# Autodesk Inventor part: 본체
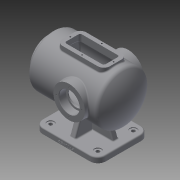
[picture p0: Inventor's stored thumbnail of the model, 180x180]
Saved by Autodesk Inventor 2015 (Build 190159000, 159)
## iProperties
Created: 2021-11
Part Number: 본체
Material: 일반
Document SubType Name: Modeling
Designer: 10259o
Density: 1 g/cm^3
Appearance: 기본값
Author: 10259o
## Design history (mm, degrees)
sketch "스케치1"
  geometry: L1 (80, -65)-(-80, -65); L2 (-80, -65)-(-80, 65); L3 (-80, 65)-(80, 65); L4 (80, 65)-(80, -65); L5 (80, -65)-(-80, 65); L6 (-80, -65)-(80, 65); 1 further point
  constraints: 12 end point, 2 midpoint, 2 parallel, 1 horizontal, 1 perpendicular
  dimensions: "d0" = 160 distance of L1.start L1.end; "d1" = 130 distance of L3.end L1.start
extrude "돌출1" new body sketch "스케치1" distance "d2" = 14; taper "d3" = 0 deg
sketch "스케치10"
  geometry: L1 (0, 0)-(0, 14) reference; 2 further points
  constraints: 1 other
  dimensions: "d49" = 5 distance of point (80, 0) point (80, 5); "d50" = 80 distance from line of L1 point (80, 5)
feature "엠보싱1" sketch "스케치10" dims "d51" = 0.5, "d52" = 0, "d61" = 100, "d62" = 200, "d63" = 65, "d64" = 20, "d65" = 114
sketch "스케치12"
  geometry: L1 (-100, 114)-(100, 114); L2 (100, 114)-(100, 179); L3 (100, 179)-(-75.993, 179); L4 (80, 0)-(80, 14) reference; L5 (80, 0)-(-80, 0) reference; A1 r 100 centre (0, 114) between (-75.993, 179) and (-100, 114); 1 further point
  constraints: 6 end point, 2 perpendicular, 2 point on circle, 1 centre point, 1 horizontal, 1 horizontal alignment
  dimensions: "d61" = 100 radius of A1; "d62" = 200 distance of L1.start L1.end; "d63" = 65 distance of L1.end L2.end; "d64" = 20 distance between parallel lines of L2 L4; "d65" = 114 distance between parallel lines of L1 L5
revolve "회전1" sketch "스케치12" stored, may be unused: angle "d66" = 90 deg
fillet "모깎기1" dims "d67" = 10
feature "쉘1" dims "d68" = 10
sketch "스케치13"
  geometry: C1 r 55 at (0, 0) reference; C2 r 65 at (0, 0) reference; C3 r 55 at (0, 0); 1 further point
  constraints: 1 centre point, 1 coincident
  dimensions: "d69" = 110 diameter of C3
extrude "돌출8" join sketch "스케치13" distance "d70" = 15; taper "d71" = 0 deg
sketch "스케치14"
  geometry: C1 r 65 at (0, 0) reference; C2 r 47.5 at (0, 0); 1 further point
  constraints: 1 centre point, 1 coincident
  dimensions: "d72" = 95 diameter of C2
extrude "돌출9" join sketch "스케치14" distance "d73" = 10; taper "d74" = 0 deg
sketch "스케치15"
  geometry: C1 r 47.5 at (0, 0) reference; C2 r 32.5 at (0, 0); 1 further point
  constraints: 1 centre point, 1 coincident
  dimensions: "d75" = 65 diameter of C2
extrude "돌출10" cut sketch "스케치15" distance "d76" = 25; taper "d77" = 0 deg
sketch "스케치16"
  geometry: C1 r 32.5 at (0, 0) reference; 2 further points
  constraints: 1 vertical alignment
  dimensions: "d78" = 40 distance of C1.centre point (0, 40)
hole "구멍3" sketch "스케치16" at (0, 40) diameter "d79" = 3.242; stored, may be unused: countersink angle "d83" = 90 deg, drill point angle "d85" = 118 deg; dims "d80" = 11, "d81" = 52, "d82" = 18, "d84" = 13
sketch "스케치17"
  geometry: L1 (-71.239, 179)-(100, 179) reference; L2 (100, 179)-(100, 161.5) reference; L3 (100, 161.5)-(110, 161.5) reference; L4 (110, 161.5)-(110, 155.621) reference; L5 (110, 155.621)-(97, 155.621) reference; L6 (97, 155.621)-(96.026, 154) reference; L7 (96.026, 154)-(97, 152.379) reference; L8 (97, 152.379)-(110, 152.379) reference; L9 (110, 152.379)-(110, 146.5) reference; L10 (110, 146.5)-(85, 146.5) reference; L11 (85, 146.5)-(85, 169) reference; L12 (85, 169)-(-71.239, 169) reference; L13 (-71.239, 59)-(85, 59) reference; L14 (85, 59)-(85, 81.5) reference; L15 (85, 81.5)-(110, 81.5) reference; L16 (110, 81.5)-(110, 75.621) reference; L17 (110, 75.621)-(97, 75.621) reference; L18 (97, 75.621)-(96.026, 74) reference; L19 (96.026, 74)-(97, 72.379) reference; L20 (97, 72.379)-(110, 72.379) reference; L21 (110, 72.379)-(110, 66.5) reference; L22 (110, 66.5)-(100, 66.5) reference; L23 (100, 66.5)-(100, 49) reference; L24 (100, 49)-(-71.239, 49) reference; L25 (-80, 0)-(-80, 14) reference; L26 (-80, 14)-(80, 14) reference; L27 (80, 14)-(80, 0) reference; L28 (80, 0)-(-80, 0) reference; C1 r 40 at (-17, 114); A1 r 100 centre (0, 114) between (-79.154, 175.111) and (-79.154, 52.889) reference; A2 r 10 centre (-71.239, 169) between (-71.239, 179) and (-79.154, 175.111) reference; A3 r 90 centre (0, 114) between (-71.239, 169) and (-71.239, 59) reference; A4 r 10 centre (-71.239, 59) between (-79.154, 52.889) and (-71.239, 49) reference; 1 further point
  constraints: 1 centre point
  dimensions: "d89" = 80 diameter of C1; "d90" = 114 distance from line of L28 C1.centre; "d91" = 127 horizontal distance of L16.end C1.centre
extrude "돌출11" join sketch "스케치17" stored distance "d92" = 150; taper "d93" = 0 deg
sketch "스케치18"
  geometry: C1 r 40 at (0, 0) reference; C2 r 21 at (0, 0); 1 further point
  constraints: 1 centre point, 1 coincident
  dimensions: "d94" = 42 diameter of C2
extrude "돌출12" cut sketch "스케치18" distance "d95" = 18; taper "d96" = 0 deg
sketch "스케치19"
  geometry: C1 r 40 at (0, 0) reference; 1 further point
hole "구멍4" sketch "스케치19" at (0, 0) diameter "d97" = 42; stored, may be unused: countersink angle "d101" = 90 deg, drill point angle "d103" = 118 deg; dims "d98" = 11, "d99" = 52, "d100" = 18, "d102" = 13
sketch "스케치20"
  geometry: C1 r 21 at (0, 0) reference; 2 further points
  constraints: 1 vertical alignment
  dimensions: "d104" = 32.5 distance of C1.centre point (0, 32.5)
hole "구멍5" sketch "스케치20" at (0, 32.5) diameter "d105" = 3.242; stored, may be unused: countersink angle "d109" = 90 deg, drill point angle "d111" = 118 deg; dims "d106" = 11, "d107" = 52, "d108" = 18, "d110" = 13
node "작업 평면2"
sketch "스케치21"
  geometry: L1 (60, -30)-(-60, -30); L2 (-60, -30)-(-60, 30); L3 (-60, 30)-(60, 30); L4 (60, 30)-(60, -30); L5 (60, -30)-(-60, 30); L6 (-60, -30)-(60, 30); 1 further point
  constraints: 12 end point, 2 midpoint, 2 parallel, 1 horizontal, 1 perpendicular
  dimensions: "d116" = 120 distance of L2.end L3.end; "d117" = 60 distance of L1.end L2.end
extrude "돌출13" join sketch "스케치21" stored distance "d118" = 18; taper "d119" = 0 deg
fillet "모깎기2" dims "d120" = 15
sketch "스케치22"
  geometry: L1 (-45, 30)-(45, 30) reference; L2 (-60, -15)-(-60, 15) reference; L3 (45, -30)-(-45, -30) reference; L4 (60, 15)-(60, -15) reference; L5 (50, 15)-(50, -15); L6 (45, -20)-(-45, -20); L7 (-50, -15)-(-50, 15); L8 (-45, 20)-(45, 20); A1 r 15 centre (45, 15) between (60, 15) and (45, 30) reference; A2 r 15 centre (-45, 15) between (-45, 30) and (-60, 15) reference; A3 r 15 centre (-45, -15) between (-60, -15) and (-45, -30) reference; A4 r 15 centre (45, -15) between (45, -30) and (60, -15) reference; A5 r 5 centre (45, 15) between (50, 15) and (45, 20); A6 r 5 centre (45, -15) between (45, -20) and (50, -15); A7 r 5 centre (-45, -15) between (-50, -15) and (-45, -20); A8 r 5 centre (-45, 15) between (-45, 20) and (-50, 15); 1 further point
  constraints: 8 end point, 8 point on circle, 4 centre point, 7 other
  dimensions: "d121" = 10 distance between parallel lines of L1 L8
extrude "돌출14" cut sketch "스케치22" distance "d122" = 70; taper "d123" = 0 deg
sketch "스케치23"
  geometry: 2 further points
  constraints: 1 vertical alignment
  dimensions: "d124" = 25 distance of point (0, 0) point (0, 25)
hole "구멍6" sketch "스케치23" at (0, 25) diameter "d125" = 3.242; stored, may be unused: countersink angle "d129" = 90 deg, drill point angle "d131" = 118 deg; dims "d126" = 9, "d127" = 52, "d128" = 18, "d130" = 11
sketch "스케치24"
  geometry: 2 further points
  constraints: 1 horizontal alignment
  dimensions: "d132" = 55 distance of point (0, 0) point (-55, 0)
hole "구멍7" sketch "스케치24" at (-55, 0) diameter "d133" = 3.242; stored, may be unused: countersink angle "d137" = 90 deg, drill point angle "d139" = 118 deg; dims "d134" = 9, "d135" = 52, "d136" = 18, "d138" = 11
sketch "스케치25"
  geometry: L1 (-65.5, 6.971)-(-65.5, 7.385) reference; L2 (-65.5, 7.385)-(-65, 7.385) reference; L3 (-65, 7.385)-(-65, 14) reference; L4 (-65, 14)-(65, 14) reference; L5 (65, 14)-(65, 0) reference; L6 (65, 0)-(-65, 0) reference; L7 (-65, 0)-(-65, 6.971) reference; L8 (-65, 6.971)-(-65.5, 6.971) reference; L9 (-20, 184)-(-20, 165.235) reference; L10 (-41.4, 150.208)-(-20, 150.208) reference; L11 (-20, 150.208)-(-20, 126.329) reference; L12 (-20, 126.329)-(-75, 126.329) reference; L13 (-75, 126.329)-(-75, 150.208) reference; L14 (-75, 150.208)-(-53.981, 150.208) reference; L15 (-30, 171.663)-(-30, 184) reference; L16 (-30, 184)-(-26.621, 184) reference; L17 (-26.621, 184)-(-26.621, 173) reference; L18 (-26.621, 173)-(-25, 172.026) reference; L19 (-25, 172.026)-(-23.379, 173) reference; L20 (-23.379, 173)-(-23.379, 184) reference; L21 (-23.379, 184)-(-20, 184) reference; L22 (20, 165.235)-(20, 184) reference; L23 (20, 184)-(23.379, 184) reference; L24 (23.379, 184)-(23.379, 173) reference; L25 (23.379, 173)-(25, 172.026) reference; L26 (25, 172.026)-(26.621, 173) reference; L27 (26.621, 173)-(26.621, 184) reference; L28 (26.621, 184)-(30, 184) reference; L29 (30, 184)-(30, 171.663) reference; L30 (53.981, 150.208)-(75, 150.208) reference; L31 (75, 150.208)-(75, 133.672) reference; L32 (75, 133.672)-(57, 133.672) reference; L33 (57, 133.672)-(57, 126.329) reference; L34 (57, 126.329)-(20, 126.329) reference; L35 (20, 126.329)-(20, 150.208) reference; L36 (20, 150.208)-(41.4, 150.208) reference; L37 (41.4, 77.792)-(-41.4, 77.792) reference; L38 (-75, 101.671)-(57, 101.671) reference; L39 (57, 101.671)-(57, 94.328) reference; L40 (57, 94.328)-(75, 94.328) reference; L41 (75, 94.328)-(75, 77.792) reference; L42 (75, 77.792)-(53.981, 77.792) reference; L43 (-53.981, 77.792)-(-75, 77.792) reference; L44 (-75, 77.792)-(-75, 101.671) reference; C1 r 55 at (0, 114); A1 r 55 centre (0, 114) between (-20, 165.235) and (-41.4, 150.208) reference; A2 r 65 centre (0, 114) between (-30, 171.663) and (-53.981, 150.208) reference; A3 r 65 centre (0, 114) between (53.981, 150.208) and (30, 171.663) reference; A4 r 55 centre (0, 114) between (41.4, 150.208) and (20, 165.235) reference; A5 r 55 centre (0, 114) between (-41.4, 77.792) and (41.4, 77.792) reference; A6 r 65 centre (0, 114) between (-53.981, 77.792) and (53.981, 77.792) reference; 1 further point
  constraints: 1 centre point, 1 coincident
  dimensions: "d140" = 110 diameter of C1
extrude "돌출15" cut sketch "스케치25" stored distance "d141" = 130; taper "d142" = 0 deg
fillet "모깎기3" dims "d149" = 20
sketch "스케치27"
  geometry: L1 (-60, 65)-(60, 65) reference; L2 (80, 45)-(80, -45) reference; L3 (60, -65)-(-60, -65) reference; L4 (-80, -45)-(-80, 45) reference; A1 r 20 centre (60, 45) between (80, 45) and (60, 65) reference; A2 r 20 centre (-60, 45) between (-60, 65) and (-80, 45) reference; A3 r 20 centre (60, 45) between (80, 45) and (60, 65) reference; A4 r 20 centre (60, -45) between (60, -65) and (80, -45) reference; A5 r 20 centre (-60, -45) between (-80, -45) and (-60, -65) reference; 1 further point
hole "구멍8" sketch "스케치27" at (60, 45) diameter "d150" = 9; stored, may be unused: countersink angle "d154" = 90 deg, drill point angle "d156" = 118 deg; dims "d151" = 8, "d152" = 18, "d153" = 2, "d155" = 14
sketch "스케치28"
  geometry: L1 (100, 161.5)-(110, 161.5) reference; L2 (110, 161.5)-(110, 155.621) reference; L3 (110, 155.621)-(97, 155.621) reference; L4 (97, 155.621)-(96.026, 154) reference; L5 (96.026, 154)-(97, 152.379) reference; L6 (97, 152.379)-(110, 152.379) reference; L7 (110, 152.379)-(110, 146.5) reference; L8 (110, 146.5)-(85, 146.5) reference; L9 (85, 146.5)-(85, 169) reference; L10 (85, 169)-(50, 169) reference; L11 (50, 169)-(50, 184) reference; L12 (50, 184)-(53.379, 184) reference; L13 (53.379, 184)-(53.379, 173) reference; L14 (53.379, 173)-(55, 172.026) reference; L15 (55, 172.026)-(56.621, 173) reference; L16 (56.621, 173)-(56.621, 184) reference; L17 (56.621, 184)-(60, 184) reference; L18 (60, 184)-(60, 179) reference; L19 (60, 179)-(100, 179) reference; L20 (100, 179)-(100, 161.5) reference; L21 (-71.239, 179)-(-60, 179) reference; L22 (-60, 179)-(-60, 184) reference; L23 (-60, 184)-(-56.621, 184) reference; L24 (-56.621, 184)-(-56.621, 173) reference; L25 (-56.621, 173)-(-55, 172.026) reference; L26 (-55, 172.026)-(-53.379, 173) reference; L27 (-53.379, 173)-(-53.379, 184) reference; L28 (-53.379, 184)-(-50, 184) reference; L29 (-50, 184)-(-50, 169) reference; L30 (-50, 169)-(-71.239, 169) reference; L31 (-71.239, 59)-(85, 59) reference; L32 (85, 59)-(85, 81.5) reference; L33 (85, 81.5)-(110, 81.5) reference; L34 (110, 81.5)-(110, 75.621) reference; L35 (110, 75.621)-(97, 75.621) reference; L36 (97, 75.621)-(96.026, 74) reference; L37 (96.026, 74)-(97, 72.379) reference; L38 (97, 72.379)-(110, 72.379) reference; L39 (110, 72.379)-(110, 66.5) reference; L40 (110, 66.5)-(100, 66.5) reference; L41 (100, 66.5)-(100, 49) reference; L42 (100, 49)-(-71.239, 49) reference; L43 (-80, 14)-(80, 14) reference; L44 (80, 14)-(80, 0) reference; L45 (80, 0)-(-80, 0) reference; L46 (-80, 0)-(-80, 14) reference; L47 (-60, 14)-(60, 14) reference; L48 (60, 14)-(47.261, 49); L49 (-69, 14)-(-51, 14) reference; L50 (-60, 14)-(-47.261, 49); L51 (0, 49)-(0, 14); A1 r 100 centre (0, 114) between (-79.154, 175.111) and (-79.154, 52.889) reference; A2 r 10 centre (-71.239, 169) between (-71.239, 179) and (-79.154, 175.111) reference; A3 r 90 centre (0, 114) between (-71.239, 169) and (-71.239, 59) reference; A4 r 10 centre (-71.239, 59) between (-79.154, 52.889) and (-71.239, 49) reference; 1 further point
  constraints: 6 end point, 4 point on line, 2 midpoint, 1 other
  dimensions: "d157" = 60 horizontal distance of point (0, 0) L48.start; "d158" = 70 deg angle of L47 L48; "d159" = 70 deg angle of L47 L50
extrude "돌출17" join sketch "스케치28" stored distance "d160" = 14; taper "d161" = 0 deg
sketch "스케치29"
  geometry: C1 r 21 at (0, 0) reference; C2 r 40 at (0, 0) reference; C3 r 26 at (0, 0); 1 further point
  constraints: 1 centre point, 1 coincident
  dimensions: "d162" = 52 diameter of C3
extrude "돌출18" cut sketch "스케치29" distance "d163" = 18; taper "d164" = 0 deg
fillet "모깎기4" dims "d165" = 0.3
fillet "모깎기5" dims "d166" = 3
fillet "모깎기6" dims "d167" = 10
fillet "모깎기7" dims "d168" = 3
chamfer "모따기1" distance "d169" = 1; stored, may be unused: second distance "d170" = 2, angle "d171" = 45 deg
sketch "스케치30"
  geometry: L1 (60, 62)-(-60, 62) reference; L2 (-77, 45)-(-77, -45) reference; L3 (-60, -62)-(60, -62) reference; L4 (77, -45)-(77, 45) reference; L5 (60, -7)-(-60, -7) reference; L6 (-60, -7)-(-60, 7) reference; L7 (-60, 7)-(60, 7) reference; L8 (60, 7)-(60, -7) reference; L9 (7, -50)-(-7, -50); L10 (-7, -50)-(-7, 50); L11 (-7, 50)-(7, 50); L12 (7, 50)-(7, -50); L13 (7, -50)-(-7, 50); L14 (-7, -50)-(7, 50); C1 r 9 at (-60, -45) reference; C2 r 9 at (-60, 45) reference; C3 r 9 at (60, -45) reference; C4 r 9 at (60, 45) reference; A1 r 17 centre (60, 45) between (77, 45) and (60, 62) reference; A2 r 17 centre (-60, 45) between (-60, 62) and (-77, 45) reference; A3 r 17 centre (-60, -45) between (-77, -45) and (-60, -62) reference; A4 r 17 centre (60, -45) between (60, -62) and (77, -45) reference; 1 further point
  constraints: 12 end point, 2 midpoint, 2 parallel, 1 horizontal, 1 perpendicular
  dimensions: "d172" = 14 distance of L10.end L11.end; "d173" = 100 distance of L11.end L9.start
extrude "돌출19" join sketch "스케치30" stored distance "d174" = 18; taper "d175" = 0 deg
feature "면 기울기1" dims angle "d176" = 20 deg
fillet "모깎기8" dims "d177" = 3
fillet "모깎기9" dims "d178" = 3
fillet "모깎기10" dims "d179" = 3
node "솔리드1"
pattern_circular "원형 패턴2" dims angle "d87" = 360 deg
pattern_circular "원형 패턴3" dims angle "d113" = 360 deg
mirror "대칭2"
mirror "대칭3"
mirror "대칭4"
mirror "대칭5"
mirror "대칭6"
node "절단 모서리 투영4"
node "절단 모서리 투영5"
node "절단 모서리 투영7"
node "절단 모서리 투영8"
node "절단 모서리 투영9"
other parameters: "d115" = 184
